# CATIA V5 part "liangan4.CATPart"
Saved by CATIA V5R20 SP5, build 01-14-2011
Part number: 连杆4
Bounding box of the stored display mesh (mm): x -20 to 170, y -20 to 20, z 0 to 40
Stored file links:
  E:\scc\liangan\liangan4.CATPart
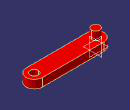
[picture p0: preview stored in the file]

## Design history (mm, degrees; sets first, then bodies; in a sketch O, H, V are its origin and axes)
Body1 (main body)
  Sketch1 on xy-plane, origin (0, 0, 0), H (1, 0, 0), V (0, 1, 0)
    construction line L1 (0, 0) -> (150, 0)
    line L2 (0, 20) -> (150, 20)
    line L3 (150, -20) -> (0, -20)
    arc A1 centre (150, 0) radius 20 from (150, 20) to (150, -20) cw
    arc A2 centre (0, 0) radius 20 from (0, -20) to (0, 20) cw
    circle A3 centre (150, 0) radius 10
    distance L1 L2 = 20
    radius A3 = 10
    horizontal: L1 H
    tangency: A1 L2, A2 L2, A1 L3, A2 L3
  Pad1: profile Sketch1, direction (0, 0, 1), length 20
  Sketch2 on end face of Pad1, origin (0, 0, 20), H (1, 0, 0), V (0, 1, 0)
    circle A1 centre (0, 0) radius 10
    radius A1 = 10
  Pad2: profile Sketch2, direction (0, 0, 1), length 20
